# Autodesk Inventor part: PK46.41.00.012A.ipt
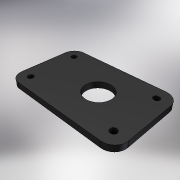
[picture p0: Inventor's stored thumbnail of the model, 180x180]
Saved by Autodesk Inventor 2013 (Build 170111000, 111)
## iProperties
Created: 2012-02
Part Number: PK46.41.00.012A.ipt
Material: Rubber
Document SubType Name: Modeling
Designer: tedescj
Density: 0.93 g/cm^3
Mass: 191.134 g
Surface Area: 496.311 cm^2
Volume: 205.521 cm^3
Author: tedescj
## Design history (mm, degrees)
sketch "Sketch1"
  geometry: L1 (15, -5)-(165, -5); L2 (185, 15)-(185, 95); L3 (165, 115)-(15, 115); L4 (-5, 95)-(-5, 15); L5 (15, 95)-(165, 95); L6 (165, 95)-(165, 15); L7 (165, 15)-(15, 15); L8 (15, 15)-(15, 95); C1 r 5 at (15, 95); C2 r 5 at (15, 15); C3 r 5 at (165, 95); C4 r 5 at (165, 15); A1 r 20 centre (15, 95) between (15, 115) and (-5, 95); A2 r 20 centre (15, 15) between (-5, 15) and (15, -5); A3 r 20 centre (165, 15) between (165, -5) and (185, 15); A4 r 20 centre (165, 95) between (185, 95) and (165, 115); 1 further point
  constraints: 16 end point, 8 centre point, 8 point on circle, 7 coincident, 4 parallel, 4 tangent, 3 equal radius, 2 horizontal, 2 perpendicular
  dimensions: "d0" = 150 distance of L5.start L5.end; "d1" = 80 distance of L5.end L6.end; "d2" = 20 distance between parallel lines of L8 L4; "d3" = 20 distance between parallel lines of L2 L6; "d4" = 20 distance between parallel lines of L1 L7; "d5" = 20 distance between parallel lines of L5 L3; "d6" = 10 diameter of C1
extrude "Extrusion1" new body sketch "Sketch1" distance "d7" = 10; taper "d8" = 0 deg
hole "Hole1" diameter "d11" = 45; stored, may be unused: countersink angle "d15" = 90 deg, drill point angle "d17" = 118 deg; dims "d9" = 80, "d10" = 60, "d12" = 6, "d13" = 4, "d14" = 2, "d16" = 8
body "Solid1"
